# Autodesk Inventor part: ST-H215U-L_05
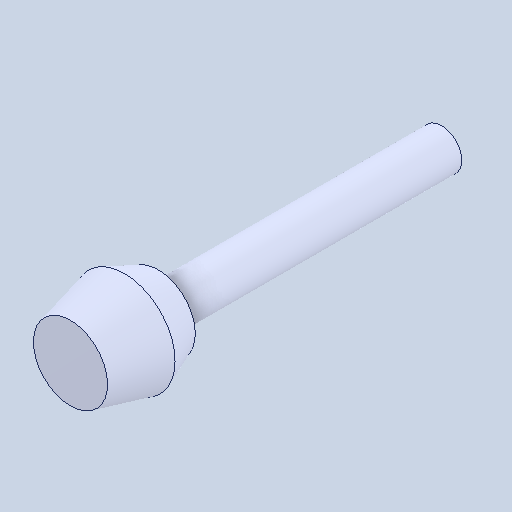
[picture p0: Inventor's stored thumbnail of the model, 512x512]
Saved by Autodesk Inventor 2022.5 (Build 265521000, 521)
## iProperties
Created: 2024-07
Part Number: ST-H215U-L_05
Material: 一般
Document SubType Name: Modeling
Designer: ImaoCorp
Density: 1 g/cm^3
Appearance: 既定
Author: ImaoCorp
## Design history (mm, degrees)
feature "ST-H215U-L_05"
node "ソリッド1"
